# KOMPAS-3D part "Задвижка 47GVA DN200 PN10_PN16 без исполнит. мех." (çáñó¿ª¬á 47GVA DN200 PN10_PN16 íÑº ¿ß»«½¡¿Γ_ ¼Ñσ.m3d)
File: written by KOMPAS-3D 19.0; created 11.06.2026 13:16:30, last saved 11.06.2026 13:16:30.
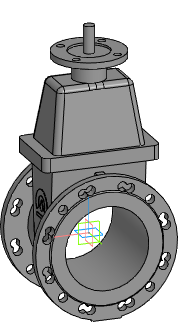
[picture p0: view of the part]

Document properties: Автор: Евгений; Полное имя файла: Z:\3.Личные\kachalov\001_3d для проектировщиков\2.2 Тип 47GVA, 47GVA.Z\_stp\_stp_Задвижка 47GVA DN40-DN1000 без исп.мех\Задвижка 47GVA DN200 PN10_PN16 без исполнит_ мех.m3d

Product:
- Part/product: Задвижка 47GVA DN200 PN10_PN16 без исполнит. мех.

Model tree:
1. Операция без истории:1  (labels: Задвижка 47GVA DN200 PN10_PN16 без исполнит. мех.)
